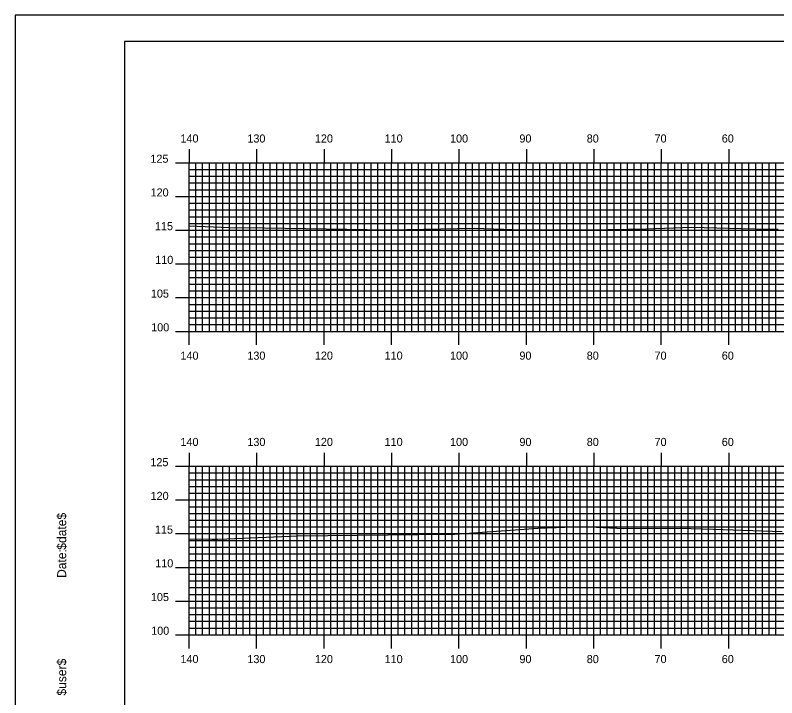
# Model space of a CAD drawing. Extents: x 1766513 to 1766856, y 442591 to 442811.
# Drawn here: x 1766513.1 to 1766626, y 442709.3 to 442810.5 of the extents above; entities that cross this region are included whole.
import ezdxf

# ---------------------------------------------------------------- set-up
doc = ezdxf.new("R2010")
doc.units = 0
for name, color, linetype in [('BORDER', 7, 'Continuous'), ('H_V ANNOTATION', 7, 'Continuous'), ('MAJOR', 7, 'Continuous'), ('MINOR', 7, 'Continuous'), ('PLOT BOUNDARY', 7, 'Continuous'), ('S_Roadway_Centerline', 7, 'Continuous')]:
    doc.layers.add(name, color=color, linetype=linetype)

msp = doc.modelspace()

# ---------------------------------------------------------------- linework, layer by layer
at = {"layer": 'BORDER'}
msp.add_lwpolyline([(1766529.31, 442596.67), (1766849.31, 442596.67), (1766849.31, 442806.67), (1766529.31, 442806.67)], close=True, dxfattribs=at)
at = {"layer": 'MAJOR'}
for p, q in [((1766538.91, 442790.67), (1766538.91, 442788.67)), ((1766548.91, 442790.67), (1766548.91, 442788.67)), ((1766558.91, 442790.67), (1766558.91, 442788.67)), ((1766568.91, 442790.67), (1766568.91, 442788.67)), ((1766578.91, 442790.67), (1766578.91, 442788.67)), ((1766588.91, 442790.67), (1766588.91, 442788.67)), ((1766598.91, 442790.67), (1766598.91, 442788.67)), ((1766608.91, 442790.67), (1766608.91, 442788.67)), ((1766618.91, 442790.67), (1766618.91, 442788.67)), ((1766536.91, 442788.67), (1766538.91, 442788.67)), ((1766538.91, 442788.67), (1766818.91, 442788.67)), ((1766538.91, 442763.67), (1766538.91, 442788.67)), ((1766538.91, 442763.67), (1766538.91, 442788.67)), ((1766538.91, 442788.67), (1766818.91, 442788.67)), ((1766548.91, 442763.67), (1766548.91, 442788.67)), ((1766558.91, 442763.67), (1766558.91, 442788.67)), ((1766568.91, 442763.67), (1766568.91, 442788.67)), ((1766578.91, 442763.67), (1766578.91, 442788.67)), ((1766588.91, 442763.67), (1766588.91, 442788.67)), ((1766598.91, 442763.67), (1766598.91, 442788.67)), ((1766608.91, 442763.67), (1766608.91, 442788.67)), ((1766618.91, 442763.67), (1766618.91, 442788.67)), ((1766536.91, 442783.67), (1766538.91, 442783.67)), ((1766538.91, 442783.67), (1766818.91, 442783.67)), ((1766536.91, 442778.67), (1766538.91, 442778.67)), ((1766538.91, 442778.67), (1766818.91, 442778.67)), ((1766536.91, 442773.67), (1766538.91, 442773.67)), ((1766538.91, 442773.67), (1766818.91, 442773.67)), ((1766536.91, 442768.67), (1766538.91, 442768.67)), ((1766538.91, 442768.67), (1766818.91, 442768.67)), ((1766536.91, 442763.67), (1766538.91, 442763.67)), ((1766538.91, 442763.67), (1766818.91, 442763.67)), ((1766538.91, 442763.67), (1766818.91, 442763.67)), ((1766538.91, 442761.66), (1766538.91, 442763.67)), ((1766548.91, 442761.66), (1766548.91, 442763.67)), ((1766558.91, 442761.66), (1766558.91, 442763.67)), ((1766568.91, 442761.66), (1766568.91, 442763.67)), ((1766578.91, 442761.66), (1766578.91, 442763.67)), ((1766588.91, 442761.66), (1766588.91, 442763.67)), ((1766598.91, 442761.66), (1766598.91, 442763.67)), ((1766608.91, 442761.66), (1766608.91, 442763.67)), ((1766618.91, 442761.66), (1766618.91, 442763.67)), ((1766538.91, 442745.67), (1766538.91, 442743.67)), ((1766548.91, 442745.67), (1766548.91, 442743.67)), ((1766558.91, 442745.67), (1766558.91, 442743.67)), ((1766568.91, 442745.67), (1766568.91, 442743.67)), ((1766578.91, 442745.67), (1766578.91, 442743.67)), ((1766588.91, 442745.67), (1766588.91, 442743.67)), ((1766598.91, 442745.67), (1766598.91, 442743.67)), ((1766608.91, 442745.67), (1766608.91, 442743.67)), ((1766618.91, 442745.67), (1766618.91, 442743.67)), ((1766536.91, 442743.67), (1766538.91, 442743.67)), ((1766538.91, 442743.67), (1766818.91, 442743.67)), ((1766538.91, 442718.67), (1766538.91, 442743.67)), ((1766538.91, 442718.67), (1766538.91, 442743.67)), ((1766538.91, 442743.67), (1766818.91, 442743.67)), ((1766548.91, 442718.67), (1766548.91, 442743.67)), ((1766558.91, 442718.67), (1766558.91, 442743.67)), ((1766568.91, 442718.67), (1766568.91, 442743.67)), ((1766578.91, 442718.67), (1766578.91, 442743.67)), ((1766588.91, 442718.67), (1766588.91, 442743.67)), ((1766598.91, 442718.67), (1766598.91, 442743.67)), ((1766608.91, 442718.67), (1766608.91, 442743.67)), ((1766618.91, 442718.67), (1766618.91, 442743.67)), ((1766536.91, 442738.67), (1766538.91, 442738.67)), ((1766538.91, 442738.67), (1766818.91, 442738.67)), ((1766536.91, 442733.67), (1766538.91, 442733.67)), ((1766538.91, 442733.67), (1766818.91, 442733.67)), ((1766536.91, 442728.67), (1766538.91, 442728.67)), ((1766538.91, 442728.67), (1766818.91, 442728.67)), ((1766536.91, 442723.67), (1766538.91, 442723.67)), ((1766538.91, 442723.67), (1766818.91, 442723.67)), ((1766536.91, 442718.67), (1766538.91, 442718.67)), ((1766538.91, 442718.67), (1766818.91, 442718.67)), ((1766538.91, 442718.67), (1766818.91, 442718.67)), ((1766538.91, 442716.66), (1766538.91, 442718.67)), ((1766548.91, 442716.66), (1766548.91, 442718.67)), ((1766558.91, 442716.66), (1766558.91, 442718.67)), ((1766568.91, 442716.66), (1766568.91, 442718.67)), ((1766578.91, 442716.66), (1766578.91, 442718.67)), ((1766588.91, 442716.66), (1766588.91, 442718.67)), ((1766598.91, 442716.66), (1766598.91, 442718.67)), ((1766608.91, 442716.66), (1766608.91, 442718.67)), ((1766618.91, 442716.66), (1766618.91, 442718.67))]:
    msp.add_line(p, q, dxfattribs=at)
at = {"layer": 'MINOR'}
for p, q in [((1766539.91, 442763.67), (1766539.91, 442788.67)), ((1766540.91, 442763.67), (1766540.91, 442788.67)), ((1766541.91, 442763.67), (1766541.91, 442788.67)), ((1766542.91, 442763.67), (1766542.91, 442788.67)), ((1766543.91, 442763.67), (1766543.91, 442788.67)), ((1766544.91, 442763.67), (1766544.91, 442788.67)), ((1766545.91, 442763.67), (1766545.91, 442788.67)), ((1766546.91, 442763.67), (1766546.91, 442788.67)), ((1766547.91, 442763.67), (1766547.91, 442788.67)), ((1766549.91, 442763.67), (1766549.91, 442788.67)), ((1766550.91, 442763.67), (1766550.91, 442788.67)), ((1766551.91, 442763.67), (1766551.91, 442788.67)), ((1766552.91, 442763.67), (1766552.91, 442788.67)), ((1766553.91, 442763.67), (1766553.91, 442788.67)), ((1766554.91, 442763.67), (1766554.91, 442788.67)), ((1766555.91, 442763.67), (1766555.91, 442788.67)), ((1766556.91, 442763.67), (1766556.91, 442788.67)), ((1766557.91, 442763.67), (1766557.91, 442788.67)), ((1766559.91, 442763.67), (1766559.91, 442788.67)), ((1766560.91, 442763.67), (1766560.91, 442788.67)), ((1766561.91, 442763.67), (1766561.91, 442788.67)), ((1766562.91, 442763.67), (1766562.91, 442788.67)), ((1766563.91, 442763.67), (1766563.91, 442788.67)), ((1766564.91, 442763.67), (1766564.91, 442788.67)), ((1766565.91, 442763.67), (1766565.91, 442788.67)), ((1766566.91, 442763.67), (1766566.91, 442788.67)), ((1766567.91, 442763.67), (1766567.91, 442788.67)), ((1766569.91, 442763.67), (1766569.91, 442788.67)), ((1766570.91, 442763.67), (1766570.91, 442788.67)), ((1766571.91, 442763.67), (1766571.91, 442788.67)), ((1766572.91, 442763.67), (1766572.91, 442788.67)), ((1766573.91, 442763.67), (1766573.91, 442788.67)), ((1766574.91, 442763.67), (1766574.91, 442788.67)), ((1766575.91, 442763.67), (1766575.91, 442788.67)), ((1766576.91, 442763.67), (1766576.91, 442788.67)), ((1766577.91, 442763.67), (1766577.91, 442788.67)), ((1766579.91, 442763.67), (1766579.91, 442788.67)), ((1766580.91, 442763.67), (1766580.91, 442788.67)), ((1766581.91, 442763.67), (1766581.91, 442788.67)), ((1766582.91, 442763.67), (1766582.91, 442788.67)), ((1766583.91, 442763.67), (1766583.91, 442788.67)), ((1766584.91, 442763.67), (1766584.91, 442788.67)), ((1766585.91, 442763.67), (1766585.91, 442788.67)), ((1766586.91, 442763.67), (1766586.91, 442788.67)), ((1766587.91, 442763.67), (1766587.91, 442788.67)), ((1766589.91, 442763.67), (1766589.91, 442788.67)), ((1766590.91, 442763.67), (1766590.91, 442788.67)), ((1766591.91, 442763.67), (1766591.91, 442788.67)), ((1766592.91, 442763.67), (1766592.91, 442788.67)), ((1766593.91, 442763.67), (1766593.91, 442788.67)), ((1766594.91, 442763.67), (1766594.91, 442788.67)), ((1766595.91, 442763.67), (1766595.91, 442788.67)), ((1766596.91, 442763.67), (1766596.91, 442788.67)), ((1766597.91, 442763.67), (1766597.91, 442788.67)), ((1766599.91, 442763.67), (1766599.91, 442788.67)), ((1766600.91, 442763.67), (1766600.91, 442788.67)), ((1766601.91, 442763.67), (1766601.91, 442788.67)), ((1766602.91, 442763.67), (1766602.91, 442788.67)), ((1766603.91, 442763.67), (1766603.91, 442788.67)), ((1766604.91, 442763.67), (1766604.91, 442788.67)), ((1766605.91, 442763.67), (1766605.91, 442788.67)), ((1766606.91, 442763.67), (1766606.91, 442788.67)), ((1766607.91, 442763.67), (1766607.91, 442788.67)), ((1766609.91, 442763.67), (1766609.91, 442788.67)), ((1766610.91, 442763.67), (1766610.91, 442788.67)), ((1766611.91, 442763.67), (1766611.91, 442788.67)), ((1766612.91, 442763.67), (1766612.91, 442788.67)), ((1766613.91, 442763.67), (1766613.91, 442788.67)), ((1766614.91, 442763.67), (1766614.91, 442788.67)), ((1766615.91, 442763.67), (1766615.91, 442788.67)), ((1766616.91, 442763.67), (1766616.91, 442788.67)), ((1766617.91, 442763.67), (1766617.91, 442788.67)), ((1766619.91, 442763.67), (1766619.91, 442788.67)), ((1766620.91, 442763.67), (1766620.91, 442788.67)), ((1766621.91, 442763.67), (1766621.91, 442788.67)), ((1766622.91, 442763.67), (1766622.91, 442788.67)), ((1766623.91, 442763.67), (1766623.91, 442788.67)), ((1766624.91, 442763.67), (1766624.91, 442788.67)), ((1766625.91, 442763.67), (1766625.91, 442788.67)), ((1766538.91, 442787.67), (1766818.91, 442787.67)), ((1766538.91, 442787.67), (1766540.91, 442787.67)), ((1766538.91, 442786.67), (1766818.91, 442786.67)), ((1766538.91, 442786.67), (1766540.91, 442786.67)), ((1766538.91, 442785.67), (1766818.91, 442785.67)), ((1766538.91, 442785.67), (1766540.91, 442785.67)), ((1766538.91, 442784.67), (1766818.91, 442784.67)), ((1766538.91, 442784.67), (1766540.91, 442784.67)), ((1766538.91, 442782.67), (1766818.91, 442782.67)), ((1766538.91, 442782.67), (1766540.91, 442782.67)), ((1766538.91, 442781.67), (1766818.91, 442781.67)), ((1766538.91, 442781.67), (1766540.91, 442781.67)), ((1766538.91, 442780.67), (1766818.91, 442780.67)), ((1766538.91, 442780.67), (1766540.91, 442780.67)), ((1766538.91, 442779.67), (1766818.91, 442779.67)), ((1766538.91, 442779.67), (1766540.91, 442779.67)), ((1766538.91, 442777.67), (1766818.91, 442777.67)), ((1766538.91, 442777.67), (1766540.91, 442777.67)), ((1766538.91, 442776.67), (1766818.91, 442776.67)), ((1766538.91, 442776.67), (1766540.91, 442776.67)), ((1766538.91, 442775.67), (1766818.91, 442775.67)), ((1766538.91, 442775.67), (1766540.91, 442775.67)), ((1766538.91, 442774.67), (1766818.91, 442774.67)), ((1766538.91, 442774.67), (1766540.91, 442774.67)), ((1766538.91, 442772.67), (1766818.91, 442772.67)), ((1766538.91, 442772.67), (1766540.91, 442772.67)), ((1766538.91, 442771.67), (1766818.91, 442771.67)), ((1766538.91, 442771.67), (1766540.91, 442771.67)), ((1766538.91, 442770.67), (1766818.91, 442770.67)), ((1766538.91, 442770.67), (1766540.91, 442770.67)), ((1766538.91, 442769.67), (1766818.91, 442769.67)), ((1766538.91, 442769.67), (1766540.91, 442769.67)), ((1766538.91, 442767.67), (1766818.91, 442767.67)), ((1766538.91, 442767.67), (1766540.91, 442767.67)), ((1766538.91, 442766.67), (1766818.91, 442766.67)), ((1766538.91, 442766.67), (1766540.91, 442766.67)), ((1766538.91, 442765.67), (1766818.91, 442765.67)), ((1766538.91, 442765.67), (1766540.91, 442765.67)), ((1766538.91, 442764.67), (1766818.91, 442764.67)), ((1766538.91, 442764.67), (1766540.91, 442764.67)), ((1766538.91, 442742.67), (1766818.91, 442742.67)), ((1766538.91, 442742.67), (1766540.91, 442742.67)), ((1766539.91, 442718.67), (1766539.91, 442743.67)), ((1766540.91, 442718.67), (1766540.91, 442743.67)), ((1766541.91, 442718.67), (1766541.91, 442743.67)), ((1766542.91, 442718.67), (1766542.91, 442743.67)), ((1766543.91, 442718.67), (1766543.91, 442743.67)), ((1766544.91, 442718.67), (1766544.91, 442743.67)), ((1766545.91, 442718.67), (1766545.91, 442743.67)), ((1766546.91, 442718.67), (1766546.91, 442743.67)), ((1766547.91, 442718.67), (1766547.91, 442743.67)), ((1766549.91, 442718.67), (1766549.91, 442743.67)), ((1766550.91, 442718.67), (1766550.91, 442743.67)), ((1766551.91, 442718.67), (1766551.91, 442743.67)), ((1766552.91, 442718.67), (1766552.91, 442743.67)), ((1766553.91, 442718.67), (1766553.91, 442743.67)), ((1766554.91, 442718.67), (1766554.91, 442743.67)), ((1766555.91, 442718.67), (1766555.91, 442743.67)), ((1766556.91, 442718.67), (1766556.91, 442743.67)), ((1766557.91, 442718.67), (1766557.91, 442743.67)), ((1766559.91, 442718.67), (1766559.91, 442743.67)), ((1766560.91, 442718.67), (1766560.91, 442743.67)), ((1766561.91, 442718.67), (1766561.91, 442743.67)), ((1766562.91, 442718.67), (1766562.91, 442743.67)), ((1766563.91, 442718.67), (1766563.91, 442743.67)), ((1766564.91, 442718.67), (1766564.91, 442743.67)), ((1766565.91, 442718.67), (1766565.91, 442743.67)), ((1766566.91, 442718.67), (1766566.91, 442743.67)), ((1766567.91, 442718.67), (1766567.91, 442743.67)), ((1766569.91, 442718.67), (1766569.91, 442743.67)), ((1766570.91, 442718.67), (1766570.91, 442743.67)), ((1766571.91, 442718.67), (1766571.91, 442743.67)), ((1766572.91, 442718.67), (1766572.91, 442743.67)), ((1766573.91, 442718.67), (1766573.91, 442743.67)), ((1766574.91, 442718.67), (1766574.91, 442743.67)), ((1766575.91, 442718.67), (1766575.91, 442743.67)), ((1766576.91, 442718.67), (1766576.91, 442743.67)), ((1766577.91, 442718.67), (1766577.91, 442743.67)), ((1766579.91, 442718.67), (1766579.91, 442743.67)), ((1766580.91, 442718.67), (1766580.91, 442743.67)), ((1766581.91, 442718.67), (1766581.91, 442743.67)), ((1766582.91, 442718.67), (1766582.91, 442743.67)), ((1766583.91, 442718.67), (1766583.91, 442743.67)), ((1766584.91, 442718.67), (1766584.91, 442743.67)), ((1766585.91, 442718.67), (1766585.91, 442743.67)), ((1766586.91, 442718.67), (1766586.91, 442743.67)), ((1766587.91, 442718.67), (1766587.91, 442743.67)), ((1766589.91, 442718.67), (1766589.91, 442743.67)), ((1766590.91, 442718.67), (1766590.91, 442743.67)), ((1766591.91, 442718.67), (1766591.91, 442743.67)), ((1766592.91, 442718.67), (1766592.91, 442743.67)), ((1766593.91, 442718.67), (1766593.91, 442743.67)), ((1766594.91, 442718.67), (1766594.91, 442743.67)), ((1766595.91, 442718.67), (1766595.91, 442743.67)), ((1766596.91, 442718.67), (1766596.91, 442743.67)), ((1766597.91, 442718.67), (1766597.91, 442743.67)), ((1766599.91, 442718.67), (1766599.91, 442743.67)), ((1766600.91, 442718.67), (1766600.91, 442743.67)), ((1766601.91, 442718.67), (1766601.91, 442743.67)), ((1766602.91, 442718.67), (1766602.91, 442743.67)), ((1766603.91, 442718.67), (1766603.91, 442743.67)), ((1766604.91, 442718.67), (1766604.91, 442743.67)), ((1766605.91, 442718.67), (1766605.91, 442743.67)), ((1766606.91, 442718.67), (1766606.91, 442743.67)), ((1766607.91, 442718.67), (1766607.91, 442743.67)), ((1766609.91, 442718.67), (1766609.91, 442743.67)), ((1766610.91, 442718.67), (1766610.91, 442743.67)), ((1766611.91, 442718.67), (1766611.91, 442743.67)), ((1766612.91, 442718.67), (1766612.91, 442743.67)), ((1766613.91, 442718.67), (1766613.91, 442743.67)), ((1766614.91, 442718.67), (1766614.91, 442743.67)), ((1766615.91, 442718.67), (1766615.91, 442743.67)), ((1766616.91, 442718.67), (1766616.91, 442743.67)), ((1766617.91, 442718.67), (1766617.91, 442743.67)), ((1766619.91, 442718.67), (1766619.91, 442743.67)), ((1766620.91, 442718.67), (1766620.91, 442743.67)), ((1766621.91, 442718.67), (1766621.91, 442743.67)), ((1766622.91, 442718.67), (1766622.91, 442743.67)), ((1766623.91, 442718.67), (1766623.91, 442743.67)), ((1766624.91, 442718.67), (1766624.91, 442743.67)), ((1766625.91, 442718.67), (1766625.91, 442743.67)), ((1766538.91, 442741.67), (1766818.91, 442741.67)), ((1766538.91, 442741.67), (1766540.91, 442741.67)), ((1766538.91, 442740.67), (1766818.91, 442740.67)), ((1766538.91, 442740.67), (1766540.91, 442740.67)), ((1766538.91, 442739.67), (1766818.91, 442739.67)), ((1766538.91, 442739.67), (1766540.91, 442739.67)), ((1766538.91, 442737.67), (1766818.91, 442737.67)), ((1766538.91, 442737.67), (1766540.91, 442737.67)), ((1766538.91, 442736.67), (1766818.91, 442736.67)), ((1766538.91, 442736.67), (1766540.91, 442736.67)), ((1766538.91, 442735.67), (1766818.91, 442735.67)), ((1766538.91, 442735.67), (1766540.91, 442735.67)), ((1766538.91, 442734.67), (1766818.91, 442734.67)), ((1766538.91, 442734.67), (1766540.91, 442734.67)), ((1766538.91, 442732.67), (1766818.91, 442732.67)), ((1766538.91, 442732.67), (1766540.91, 442732.67)), ((1766538.91, 442731.67), (1766818.91, 442731.67)), ((1766538.91, 442731.67), (1766540.91, 442731.67)), ((1766538.91, 442730.67), (1766818.91, 442730.67)), ((1766538.91, 442730.67), (1766540.91, 442730.67)), ((1766538.91, 442729.67), (1766818.91, 442729.67)), ((1766538.91, 442729.67), (1766540.91, 442729.67)), ((1766538.91, 442727.67), (1766818.91, 442727.67)), ((1766538.91, 442727.67), (1766540.91, 442727.67)), ((1766538.91, 442726.67), (1766818.91, 442726.67)), ((1766538.91, 442726.67), (1766540.91, 442726.67)), ((1766538.91, 442725.67), (1766818.91, 442725.67)), ((1766538.91, 442725.67), (1766540.91, 442725.67)), ((1766538.91, 442724.67), (1766818.91, 442724.67)), ((1766538.91, 442724.67), (1766540.91, 442724.67)), ((1766538.91, 442722.67), (1766818.91, 442722.67)), ((1766538.91, 442722.67), (1766540.91, 442722.67)), ((1766538.91, 442721.67), (1766818.91, 442721.67)), ((1766538.91, 442721.67), (1766540.91, 442721.67)), ((1766538.91, 442720.67), (1766818.91, 442720.67)), ((1766538.91, 442720.67), (1766540.91, 442720.67)), ((1766538.91, 442719.67), (1766818.91, 442719.67)), ((1766538.91, 442719.67), (1766540.91, 442719.67))]:
    msp.add_line(p, q, dxfattribs=at)
at = {"layer": 'PLOT BOUNDARY'}
msp.add_lwpolyline([(1766513.12, 442590.55), (1766853.12, 442590.55), (1766853.12, 442810.55), (1766513.12, 442810.55)], close=True, dxfattribs=at)
at = {"layer": 'S_Roadway_Centerline'}
for points in [[(1766538.91, 442779.32), (1766544.89, 442779.09), (1766550.09, 442779.02), (1766568.39, 442778.71), (1766568.61, 442778.74), (1766568.73, 442778.72), (1766581.17, 442778.95), (1766588.37, 442778.71), (1766601.04, 442778.78), (1766606.73, 442778.87), (1766613.39, 442779.12), (1766624.73, 442778.8), (1766626.23, 442778.81)], [(1766538.91, 442732.9), (1766542.29, 442732.86), (1766543.11, 442732.87), (1766544.52, 442732.89), (1766554.97, 442733.37), (1766577.36, 442733.6), (1766578.3, 442733.6), (1766590.65, 442734.49), (1766597.28, 442734.74), (1766603.33, 442734.44), (1766611.72, 442734.46), (1766616.64, 442734.31), (1766626.82, 442733.97)]]:
    msp.add_lwpolyline(points, dxfattribs=at)

# ---------------------------------------------------------------- texts
at = {"layer": 'BORDER'}
for s, p in [('$date$', (1766520.68, 442731.28)), ('Date:', (1766520.68, 442727.1)), ('$user$', (1766520.68, 442709.65))]:
    msp.add_text(s, height=1.339, rotation=90, dxfattribs=at).set_placement(p)
at = {"layer": 'H_V ANNOTATION'}
for s, p in [('140', (1766537.62, 442791.67)), ('130', (1766547.54, 442791.67)), ('120', (1766557.55, 442791.67)), ('110', (1766567.89, 442791.67)), ('100', (1766577.59, 442791.67)), ('90', (1766587.88, 442791.67)), ('80', (1766597.86, 442791.67)), ('70', (1766607.91, 442791.67)), ('60', (1766617.88, 442791.67)), ('125', (1766533.16, 442788.67)), ('120', (1766533.19, 442783.67)), ('115', (1766533.84, 442778.67)), ('110', (1766533.88, 442773.67)), ('105', (1766533.24, 442768.67)), ('100', (1766533.28, 442763.67)), ('140', (1766537.62, 442759.47)), ('130', (1766547.54, 442759.47)), ('120', (1766557.55, 442759.47)), ('110', (1766567.89, 442759.47)), ('100', (1766577.59, 442759.47)), ('90', (1766587.88, 442759.47)), ('80', (1766597.86, 442759.47)), ('70', (1766607.91, 442759.47)), ('60', (1766617.88, 442759.47)), ('140', (1766537.62, 442746.67)), ('130', (1766547.54, 442746.67)), ('120', (1766557.55, 442746.67)), ('110', (1766567.89, 442746.67)), ('100', (1766577.59, 442746.67)), ('90', (1766587.88, 442746.67)), ('80', (1766597.86, 442746.67)), ('70', (1766607.91, 442746.67)), ('60', (1766617.88, 442746.67)), ('125', (1766533.16, 442743.67)), ('120', (1766533.19, 442738.67)), ('115', (1766533.84, 442733.67)), ('110', (1766533.88, 442728.67)), ('105', (1766533.24, 442723.67)), ('100', (1766533.28, 442718.67)), ('140', (1766537.62, 442714.47)), ('130', (1766547.54, 442714.47)), ('120', (1766557.55, 442714.47)), ('110', (1766567.89, 442714.47)), ('100', (1766577.59, 442714.47)), ('90', (1766587.88, 442714.47)), ('80', (1766597.86, 442714.47)), ('70', (1766607.91, 442714.47)), ('60', (1766617.88, 442714.47))]:
    msp.add_text(s, height=1.2, dxfattribs=at).set_placement(p)
at = {"layer": 'MAJOR'}
for p in [(1766538.9, 442763.67), (1766538.9, 442718.67)]:
    msp.add_text('-', height=0.012, dxfattribs=at).set_placement(p)

doc.saveas('drawing.dxf')
